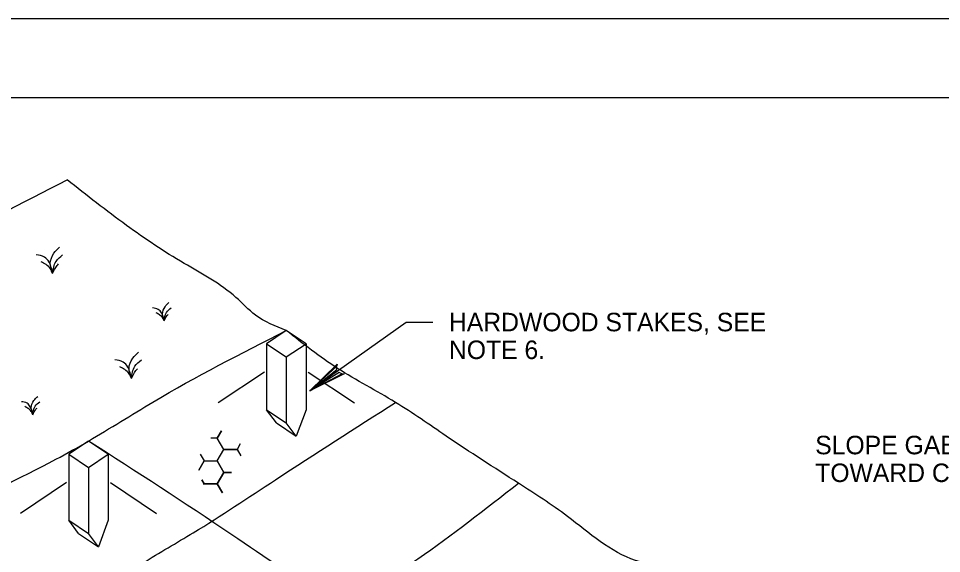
# Model space of a CAD drawing. Extents: x 3 to 3592, y -602 to 1171.
# Drawn here: x 389.1 to 563.9, y 1069.6 to 1170.8 of the extents above; entities that cross this region are included whole.
import ezdxf

# ---------------------------------------------------------------- set-up
doc = ezdxf.new("R2010")
doc.units = 0
for name, color, linetype in [('1', 7, 'Continuous'), ('2', 7, 'Continuous'), ('3', 7, 'Continuous'), ('PLT-BNDY', 7, 'Continuous')]:
    doc.layers.add(name, color=color, linetype=linetype)

msp = doc.modelspace()

# ---------------------------------------------------------------- linework, layer by layer
at = {"layer": '1'}
msp.add_lwpolyline([(827.51, 591.83), (827.51, 1155.83), (41.51, 1155.83), (41.51, 591.83), (827.51, 591.83), (827.51, 618.19), (627.51, 618.19), (627.51, 682.87), (827.51, 682.87), (827.51, 711.83), (627.51, 711.83), (627.51, 591.83), (706.31, 591.83), (706.31, 618.19), (706.31, 591.83), (783.31, 591.83), (783.31, 618.19), (783.31, 605.88), (827.51, 605.88)], dxfattribs=at)
at = {"layer": '2'}
for p, q in [((436.1, 1109.27), (436.1, 1096.77)), ((443.6, 1109.27), (443.6, 1096.77)), ((443.6, 1109.27), (443.6, 1109.27)), ((439.85, 1106.77), (439.85, 1094.27)), ((435.71, 1103.9), (426.96, 1098.07)), ((443.6, 1103.9), (443.6, 1103.9)), ((443.99, 1103.9), (452.74, 1098.07)), ((436.1, 1096.77), (439.85, 1094.27)), ((437.97, 1094.27), (436.1, 1096.77)), ((443.6, 1096.77), (441.72, 1091.77)), ((437.97, 1094.27), (441.72, 1091.77)), ((441.72, 1091.77), (439.85, 1094.27)), ((398.66, 1088.35), (398.66, 1075.85)), ((406.16, 1088.35), (406.16, 1075.85)), ((406.16, 1088.35), (406.16, 1088.35)), ((402.41, 1085.85), (402.41, 1073.35)), ((398.27, 1082.97), (389.52, 1077.14)), ((406.16, 1082.97), (406.16, 1082.97)), ((406.55, 1082.97), (415.3, 1077.14)), ((398.66, 1075.85), (402.41, 1073.35)), ((400.54, 1073.35), (398.66, 1075.85)), ((406.16, 1075.85), (404.29, 1070.85)), ((400.54, 1073.35), (404.29, 1070.85)), ((404.29, 1070.85), (402.41, 1073.35))]:
    msp.add_line(p, q, dxfattribs=at)
for points in [[(439.85, 1111.77), (436.1, 1109.27), (439.85, 1106.77), (443.6, 1109.27)], [(402.41, 1090.85), (398.66, 1088.35), (402.41, 1085.85), (406.16, 1088.35)]]:
    msp.add_lwpolyline(points, close=True, dxfattribs=at)
for points in [[(467.58, 1113.29), (462.58, 1113.29), (444.29, 1100.35)], [(450.34, 1103.58), (449.85, 1103.84), (444.29, 1100.35), (450.34, 1103.58), (450.8, 1103.54), (444.29, 1100.35), (449.45, 1104.39), (449.36, 1104.93), (444.29, 1100.35), (449.48, 1105.41), (449.36, 1104.93)], [(427.58, 1092.78), (426.79, 1091.41)], [(426.79, 1091.41), (427.58, 1092.78)], [(426.79, 1091.41), (425.54, 1091.41)], [(428.04, 1089.25), (426.79, 1091.41)], [(426.79, 1087.08), (428.04, 1089.25)], [(428.04, 1089.25), (430.54, 1089.25)], [(430.54, 1089.25), (428.04, 1089.25)], [(431.15, 1090.3), (430.54, 1089.25)], [(430.54, 1089.25), (431.23, 1088.05)], [(423.56, 1088.34), (424.29, 1087.08)], [(424.29, 1087.08), (423.29, 1085.34)], [(423.29, 1085.34), (424.29, 1087.08)], [(424.29, 1087.08), (426.79, 1087.08)], [(426.79, 1087.08), (428.04, 1084.92)], [(428.04, 1084.92), (426.79, 1087.08)], [(428.04, 1084.92), (426.79, 1082.75)], [(426.79, 1082.75), (428.04, 1084.92)], [(428.04, 1084.92), (429.51, 1084.92)], [(429.51, 1084.92), (428.04, 1084.92)], [(423.86, 1083.49), (424.29, 1082.75)], [(424.29, 1082.75), (423.86, 1083.49)], [(424.29, 1082.75), (424.2, 1082.6)], [(424.2, 1082.6), (424.29, 1082.75)], [(424.29, 1082.75), (426.79, 1082.75)], [(426.79, 1082.75), (424.29, 1082.75)], [(426.79, 1082.75), (427.77, 1081.05)], [(427.77, 1081.05), (426.79, 1082.75)]]:
    msp.add_lwpolyline(points, dxfattribs=at)
for points in [[(267.2, 1066.01), (282.31, 1075.46), (298.6, 1083.74), (312.62, 1091.25), (315.81, 1093.12), (334.11, 1105.1), (354.74, 1115.91), (360.92, 1119.37), (373.09, 1126.73), (398.36, 1140.29)], [(439.85, 1111.77), (434.01, 1114.7), (430.32, 1118.04), (420.5, 1124.48), (409.6, 1131.67), (398.36, 1140.29)], [(395.62, 1122.55), (395.17, 1124.43), (395.87, 1126.39), (396.94, 1127.53)], [(395.62, 1122.55), (394.93, 1124.72), (394.05, 1125.67), (392.5, 1126.07)], [(395.62, 1122.55), (396.26, 1124.86), (397.51, 1126.07)], [(395.62, 1122.55), (395.18, 1123.47), (394.36, 1124.24), (393.44, 1124.76)], [(395.62, 1122.55), (396.46, 1124.06), (396.75, 1124.38)], [(416.72, 1113.57), (416.41, 1114.89), (416.9, 1116.26), (417.64, 1117.06)], [(416.72, 1113.57), (416.24, 1115.09), (415.62, 1115.76), (414.54, 1116.04)], [(416.72, 1113.57), (416.41, 1114.21), (415.84, 1114.75), (415.2, 1115.12)], [(416.72, 1113.57), (417.17, 1115.19), (418.05, 1116.04)], [(416.72, 1113.57), (417.31, 1114.63), (417.51, 1114.85)], [(309.52, 1038.47), (323.8, 1046.94), (340.09, 1055.22), (354.11, 1062.73), (357.31, 1064.6), (375.6, 1076.58), (396.23, 1087.39), (402.41, 1090.85), (414.58, 1098.21), (439.85, 1111.77)], [(532.05, 1065.66), (517.11, 1066.97), (505.99, 1068.26), (493.08, 1076.58), (483.79, 1082.87), (470.12, 1091.8), (460.54, 1098.16), (449.56, 1104.61), (439.85, 1111.77)], [(410.53, 1102.67), (410.08, 1104.55), (410.78, 1106.51), (411.85, 1107.65)], [(410.53, 1102.67), (409.84, 1104.84), (408.96, 1105.79), (407.41, 1106.19)], [(410.53, 1102.67), (410.08, 1103.59), (409.27, 1104.36), (408.35, 1104.88)], [(410.53, 1102.67), (411.17, 1104.99), (412.42, 1106.19)], [(410.53, 1102.67), (411.37, 1104.18), (411.66, 1104.5)], [(338.76, 1019.24), (353.44, 1028.52), (368.12, 1037.6), (381.74, 1046.23), (395.89, 1056.02), (412.71, 1067.77), (422.24, 1073.49), (437.81, 1083.52), (460.54, 1098.16)], [(391.87, 1095.82), (391.39, 1097.34), (390.77, 1098.01), (389.69, 1098.29)], [(391.87, 1095.82), (391.56, 1097.14), (392.05, 1098.51), (392.79, 1099.31)], [(391.87, 1095.82), (392.32, 1097.44), (393.2, 1098.29)], [(391.87, 1095.82), (391.56, 1096.46), (390.99, 1097), (390.35, 1097.37)], [(391.87, 1095.82), (392.46, 1096.88), (392.66, 1097.1)], [(504.17, 1040.32), (489.07, 1042.14), (474.74, 1043.26), (459.7, 1053.35), (448.49, 1060.56), (429.53, 1073.11), (402.41, 1090.85)], [(368, 1000), (385.48, 1012.77), (409.69, 1028.95), (423.39, 1039.73), (448.89, 1058.04), (464.78, 1068.57), (483.79, 1082.87)]]:
    msp.add_spline(points, degree=3, dxfattribs=at)
at = {"layer": 'PLT-BNDY'}
msp.add_lwpolyline([(2.51, 1170.83), (843.51, 1170.83), (843.51, 576.83), (2.51, 576.83)], close=True, dxfattribs=at)

# ---------------------------------------------------------------- texts
at = {"layer": '3'}
for s, p in [('HARDWOOD STAKES, SEE', (470.65, 1111.62)), ('NOTE 6.', (470.65, 1106.37)), ('SLOPE GABIONS', (540, 1088.34)), ('TOWARD CHANNEL', (540, 1083.09))]:
    msp.add_text(s, height=3.5, dxfattribs=at).set_placement(p)

doc.saveas('drawing.dxf')
